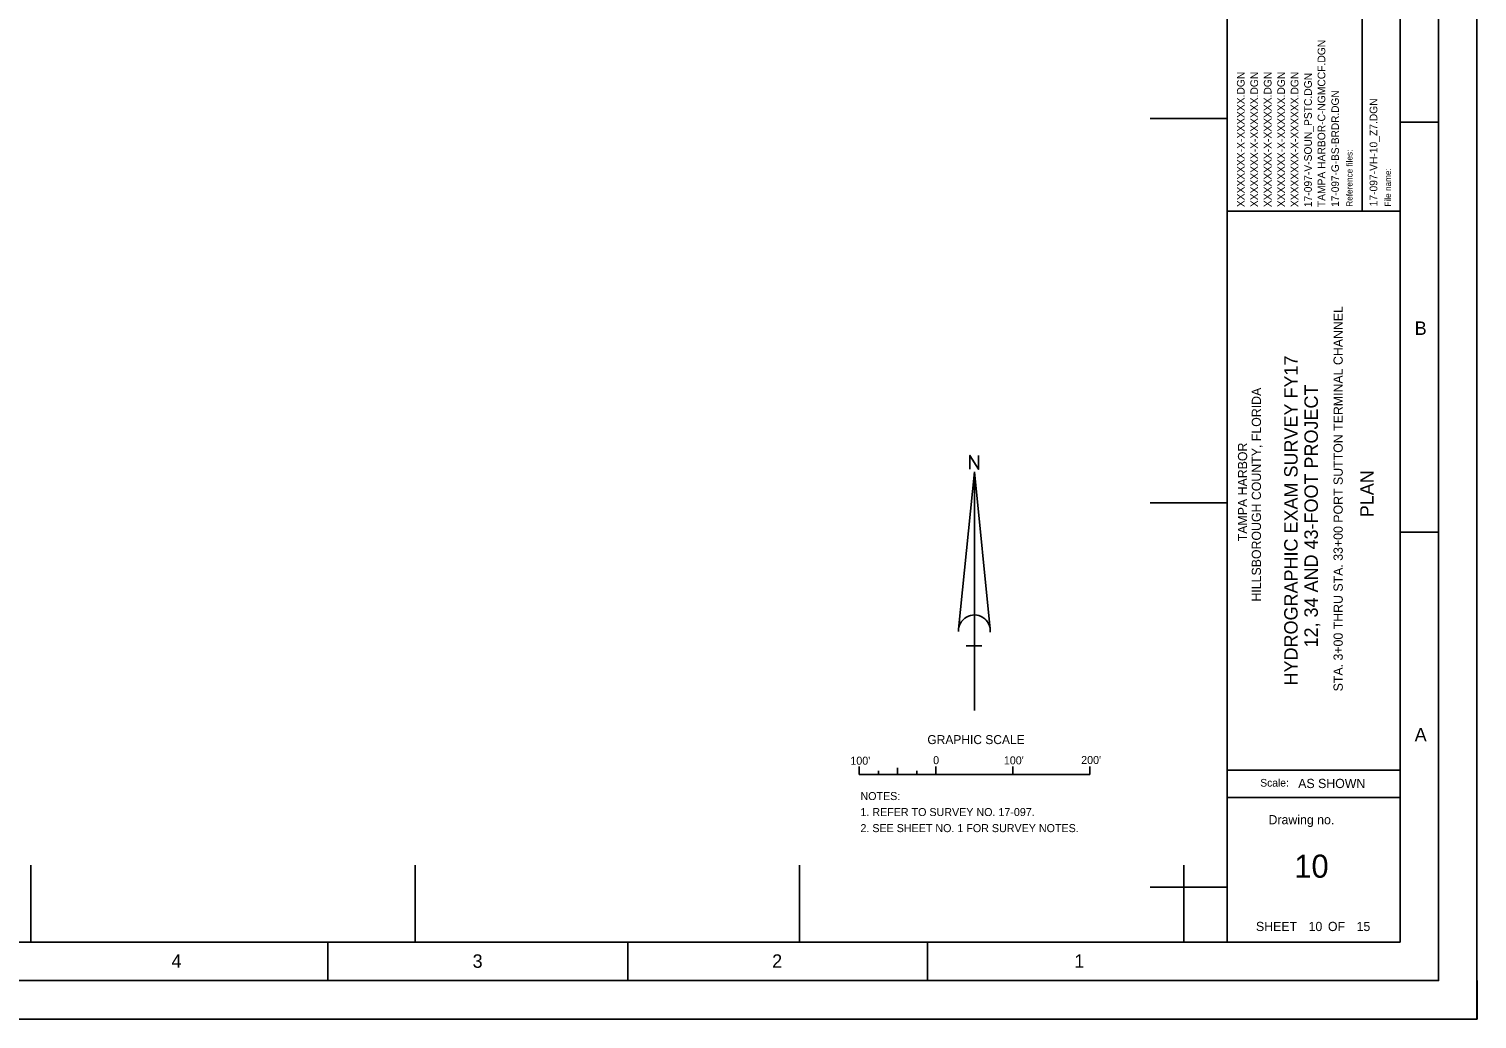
# Model space of a CAD drawing. Extents: x 517982 to 522382, y 1296329 to 1299729.
# Drawn here: x 520497 to 522382, y 1296329 to 1297616 of the extents above; entities that cross this region are included whole.
import ezdxf

# ---------------------------------------------------------------- set-up
doc = ezdxf.new("R2010")
doc.units = 0
for name, color, linetype in [('G-ANNO-NPLT', 7, 'Continuous'), ('G-ANNO-TEXT-DRWG', 7, 'Continuous'), ('G-ANNO-TEXT-PROJ', 7, 'Continuous'), ('G-ANNO-TEXT-TTLB', 7, 'Continuous'), ('G-ANNO-TTLB', 7, 'Continuous'), ('V-ANNO-NOTE', 7, 'Continuous'), ('V-ANNO-SYMB', 7, 'Continuous'), ('V-TOPO-COOR-STAT', 7, 'Continuous')]:
    doc.layers.add(name, color=color, linetype=linetype)

msp = doc.modelspace()

# ---------------------------------------------------------------- linework, layer by layer
at = {"layer": 'G-ANNO-NPLT'}
msp.add_lwpolyline([(517981.5, 1299728.6), (522381.5, 1299728.6), (522381.5, 1296328.6), (517981.5, 1296328.6)], close=True, dxfattribs=at)
msp.add_lwpolyline([(522381.6, 1296378.6), (522381.6, 1296328.6), (522331.6, 1296328.6)], dxfattribs=at)
at = {"layer": 'G-ANNO-TTLB'}
for p, q in [((522056.5, 1299628.6), (522056.5, 1296428.6)), ((522232.2, 1297730.7), (522232.2, 1297379.3)), ((522331.5, 1297495.2), (522281.5, 1297495.2)), ((522056.5, 1297379.3), (522281.5, 1297379.3)), ((522331.5, 1296961.9), (522281.5, 1296961.9)), ((522056.5, 1296652.3), (522281.5, 1296652.3)), ((522056.5, 1296616.6), (522281.5, 1296616.6)), ((520886.5, 1296378.6), (520886.5, 1296428.6)), ((521276.5, 1296378.6), (521276.5, 1296428.6)), ((521666.5, 1296378.6), (521666.5, 1296428.6))]:
    msp.add_line(p, q, dxfattribs=at)
for points in [[(518031.5, 1296378.6), (522331.5, 1296378.6), (522331.5, 1299678.6), (518031.5, 1299678.6)], [(522281.5, 1299628.6), (518156.5, 1299628.6), (518156.5, 1296428.6), (522281.5, 1296428.6)]]:
    msp.add_lwpolyline(points, close=True, dxfattribs=at)
at = {"layer": 'V-ANNO-NOTE'}
for p, q in [((521577.6, 1296646.6), (521577.6, 1296657.1)), ((521677.6, 1296646.6), (521677.6, 1296657.1)), ((521677.6, 1296646.6), (521677.6, 1296657.1)), ((521777.6, 1296646.6), (521777.6, 1296657.1)), ((521877.6, 1296646.6), (521877.6, 1296657.1)), ((521577.6, 1296646.6), (521877.6, 1296646.6)), ((521602.6, 1296646.6), (521602.6, 1296651.4)), ((521627.6, 1296646.6), (521627.6, 1296655.2)), ((521652.6, 1296646.6), (521652.6, 1296651.4)), ((521677.6, 1296646.6), (521677.6, 1296651.6))]:
    msp.add_line(p, q, dxfattribs=at)
at = {"layer": 'V-ANNO-SYMB'}
for p, q in [((521707, 1296835.6), (521727.6, 1297040.4)), ((521727.6, 1296730.1), (521727.6, 1297040.4)), ((521748.1, 1296835.6), (521727.6, 1297040.4)), ((521737.4, 1296813.9), (521716.7, 1296813.9))]:
    msp.add_line(p, q, dxfattribs=at)
msp.add_lwpolyline([(521721.8, 1297043.7), (521721.8, 1297061.8), (521733.1, 1297043.7), (521733.1, 1297061.8)], dxfattribs=at)
msp.add_arc((521727.6, 1296833.5), 20.7, 355.2984, 182.0673, dxfattribs=at)
at = {"layer": 'V-TOPO-COOR-STAT'}
for p, q in [((522056.5, 1297500), (521956.5, 1297500)), ((522056.5, 1297000), (521956.5, 1297000)), ((520500, 1296428.6), (520500, 1296528.6)), ((521000, 1296428.6), (521000, 1296528.6)), ((521500, 1296428.6), (521500, 1296528.6)), ((522000, 1296428.6), (522000, 1296528.6)), ((522056.5, 1296500), (521956.5, 1296500))]:
    msp.add_line(p, q, dxfattribs=at)

# ---------------------------------------------------------------- texts
at = {"layer": 'G-ANNO-TEXT-DRWG'}
for s, height, p in [('TAMPA HARBOR-C-NGMCCF.DGN', 10, (522184.2, 1297384.7)), ('XXXXXXXX-X-XXXXXX.DGN', 10, (522079.2, 1297384.7)), ('XXXXXXXX-X-XXXXXX.DGN', 10, (522096.7, 1297384.7)), ('XXXXXXXX-X-XXXXXX.DGN', 10, (522114.2, 1297384.7)), ('XXXXXXXX-X-XXXXXX.DGN', 10, (522131.7, 1297384.7)), ('XXXXXXXX-X-XXXXXX.DGN', 10, (522149.2, 1297384.7)), ('17-097-V-SOUN_PSTC.DGN', 10, (522166.7, 1297384.7)), ('17-097-VH-10_Z7.DGN', 10, (522251.9, 1297385.7)), ('STA. 3+00 THRU STA. 33+00 PORT SUTTON TERMINAL CHANNEL', 12, (522206.9, 1296754.8)), ('PLAN', 17.5, (522247.1, 1296981.3))]:
    msp.add_text(s, height=height, rotation=90, dxfattribs=at).set_placement(p)
for s, height, p in [('10', 30, (522143.9, 1296512.4)), (' 10          15', 12, (522158, 1296443))]:
    msp.add_text(s, height=height, dxfattribs=at).set_placement(p)
at = {"layer": 'G-ANNO-TEXT-PROJ'}
for s, height, p in [('17-097-G-BS-BRDR.DGN', 9.8, (522201.9, 1297385.1)), ('HYDROGRAPHIC EXAM SURVEY FY17', 17.5, (522148.2, 1296762.5)), ('HILLSBOROUGH COUNTY, FLORIDA', 12, (522100.5, 1296871.6)), ('12, 34 AND 43-FOOT PROJECT', 17.5, (522174.5, 1296811.9)), ('TAMPA HARBOR', 12, (522082.5, 1296950))]:
    msp.add_text(s, height=height, rotation=90, dxfattribs=at).set_placement(p)
at = {"layer": 'G-ANNO-TEXT-TTLB'}
for s, p in [('Reference files:', (522219.6, 1297385.2)), ('File name:', (522269.6, 1297385.4))]:
    msp.add_text(s, height=8, rotation=90, dxfattribs=at).set_placement(p)
for s, height, p in [('Scale:', 10, (522099.6, 1296630.9)), ('AS SHOWN', 12, (522148.9, 1296629)), ('Drawing no.', 12, (522110.3, 1296581.9)), ('SHEET         OF', 12, (522094, 1296443))]:
    msp.add_text(s, height=height, dxfattribs=at).set_placement(p)
at = {"layer": 'G-ANNO-TTLB'}
for s, p in [('B', (522300.5, 1297218.5)), ('A', (522300.5, 1296689.8)), ('4', (520682.8, 1296395.2)), ('3', (521074.7, 1296395.2)), ('2', (521464.4, 1296395.2)), ('1', (521857.6, 1296395.2))]:
    msp.add_text(s, height=17.5, dxfattribs=at).set_placement(p)
at = {"layer": 'V-ANNO-NOTE'}
for s, height, p in [('GRAPHIC SCALE', 11.666, (521666.4, 1296686.2)), ("100'", 10.42, (521566.2, 1296659.4)), ('0', 10.4, (521673.9, 1296660.1)), ("100'", 10.42, (521765.9, 1296659.8)), ("200'", 10.42, (521866.5, 1296660.3)), ('NOTES:', 10.42, (521579.3, 1296613.4)), ('1. REFER TO SURVEY NO. 17-097.', 10.416, (521579.3, 1296592.6)), ('2. SEE SHEET NO. 1 FOR SURVEY NOTES.', 10.416, (521579.3, 1296571.7))]:
    msp.add_text(s, height=height, dxfattribs=at).set_placement(p)

doc.saveas('drawing.dxf')
